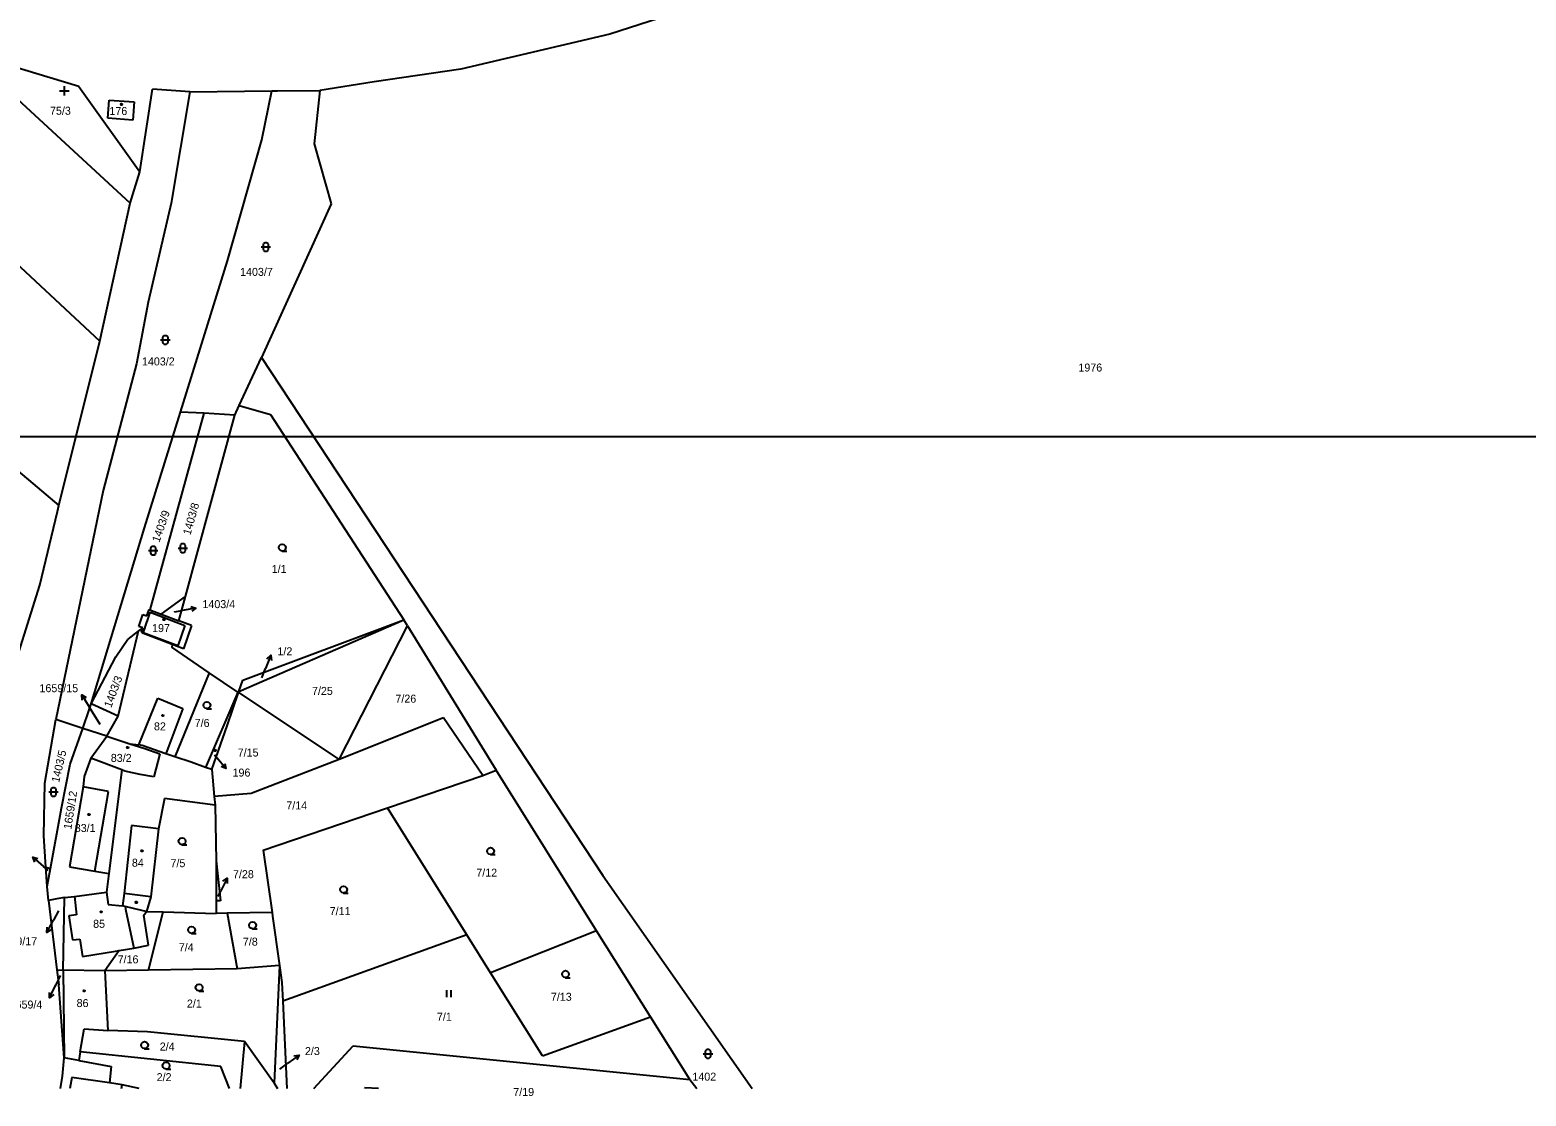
# Model space of a CAD drawing. Extents: x -801853 to -800578, y -1017479 to -1016338.
# Drawn here: x -801488.1 to -801170.2, y -1017479.3 to -1017252.6 of the extents above; entities that cross this region are included whole.
import ezdxf

# ---------------------------------------------------------------- set-up
doc = ezdxf.new("R2010")
doc.units = 0
for name, color, linetype in [('Default', 7, 'Continuous'), ('KN_HRANICE', 7, 'Continuous'), ('KN_KULTURY', 7, 'Continuous'), ('KN_PARCELY', 7, 'Continuous'), ('KN_SLUCKY', 7, 'Continuous'), ('LEGENDA', 7, 'Continuous')]:
    doc.layers.add(name, color=color, linetype=linetype)

# ---------------------------------------------------------------- blocks, each defined once
blk = doc.blocks.new('304')
at = {"layer": 'Default'}
blk.add_lwpolyline([(0, 0), (-0.38, 0.1), (-0.65, 0.37), (-0.75, 0.74), (-0.65, 1.11), (-0.38, 1.38), (-0.01, 1.48), (0.36, 1.38), (0.63, 1.11), (0.73, 0.73), (0.63, 0.35), (0.36, 0.08), (-0.02, -0.02), (0.98, -0.02)], dxfattribs=at)
blk = doc.blocks.new('306')
at = {"layer": 'Default'}
for p, q in [((-0.5, 1.5), (-0.5, 0)), ((0.5, 0), (0.5, 1.5))]:
    blk.add_line(p, q, dxfattribs=at)
blk = doc.blocks.new('315')
at = {"layer": 'Default'}
for p, q in [((-1, 1), (1, 1)), ((0, 0), (0, 2))]:
    blk.add_line(p, q, dxfattribs=at)
blk = doc.blocks.new('316')
at = {"layer": 'Default'}
for points in [[(-1, 1), (0.27, 1), (1, 1)], [(-0.5, 1.5), (-0.4, 1.79), (-0.15, 1.97), (0.16, 1.97), (0.41, 1.79), (0.51, 1.5), (0.51, 0.5), (0.41, 0.21), (0.16, 0.03), (-0.15, 0.03), (-0.4, 0.21), (-0.5, 0.5), (-0.5, 1.5)]]:
    blk.add_lwpolyline(points, dxfattribs=at)
blk = doc.blocks.new('NAHRADNI_SYMBOL')
at = {"layer": 'Default'}
blk.add_lwpolyline([(0.09, 0.15), (0.18, 0), (0.09, -0.15), (-0.09, -0.15), (-0.18, 0), (-0.09, 0.15), (0.09, 0.15)], dxfattribs=at)
blk = doc.blocks.new('10292')
at = {"layer": 'Default'}
blk.add_line((0, 3), (0, 0), dxfattribs=at)
blk.add_lwpolyline([(-0.5, 2), (0, 3), (0.5, 2)], dxfattribs=at)
blk = doc.blocks.new('402')
at = {"layer": 'Default'}
blk.add_lwpolyline([(0.09, 0.15), (0.18, 0), (0.09, -0.15), (-0.09, -0.15), (-0.18, 0), (-0.09, 0.15), (0.09, 0.15)], dxfattribs=at)

msp = doc.modelspace()

# ---------------------------------------------------------------- linework, layer by layer
at = {"layer": 'KN_HRANICE'}
for p, q in [((-801619.51, -1017238.39), (-801481.95, -1017353.71)), ((-801318.92, -1017238.69), (-801364.93, -1017253.53)), ((-801364.93, -1017253.53), (-801396.54, -1017260.97)), ((-801477.73, -1017264.63), (-801501.56, -1017257.45)), ((-801466.82, -1017289.45), (-801501.56, -1017257.45)), ((-801396.54, -1017260.97), (-801415.01, -1017263.64)), ((-801477.73, -1017264.63), (-801464.79, -1017282.78)), ((-801464.79, -1017282.78), (-801462.07, -1017265.26)), ((-801454.13, -1017265.82), (-801462.07, -1017265.26)), ((-801415.01, -1017263.64), (-801426.49, -1017265.49)), ((-801471.6, -1017271.43), (-801471.3, -1017267.55)), ((-801471.3, -1017267.55), (-801466, -1017267.95)), ((-801466, -1017267.95), (-801466.29, -1017271.83)), ((-801454.13, -1017265.82), (-801458.15, -1017289.48)), ((-801454.13, -1017265.82), (-801436.73, -1017265.61)), ((-801438.87, -1017276.02), (-801436.73, -1017265.61)), ((-801436.73, -1017265.61), (-801435.52, -1017265.6)), ((-801435.52, -1017265.6), (-801426.49, -1017265.49)), ((-801426.49, -1017265.49), (-801427.72, -1017276.85)), ((-801466.29, -1017271.83), (-801471.6, -1017271.43)), ((-801473.28, -1017318.78), (-801518.94, -1017276.33)), ((-801446.14, -1017301.75), (-801438.87, -1017276.02)), ((-801427.72, -1017276.85), (-801424.14, -1017289.58)), ((-801466.82, -1017289.45), (-801464.79, -1017282.78)), ((-801473.28, -1017318.78), (-801466.82, -1017289.45)), ((-801458.15, -1017289.48), (-801462.97, -1017310.53)), ((-801424.14, -1017289.58), (-801438.92, -1017322.27)), ((-801456.12, -1017333.87), (-801446.14, -1017301.75)), ((-801462.97, -1017310.53), (-801465.45, -1017323.65)), ((-801481.95, -1017353.71), (-801473.28, -1017318.78)), ((-801443.65, -1017332.48), (-801438.92, -1017322.27)), ((-801438.92, -1017322.27), (-801366.39, -1017432.38)), ((-801465.45, -1017323.65), (-801472.56, -1017350.57)), ((-801463.78, -1017358.51), (-801456.12, -1017333.87)), ((-801451.19, -1017334.14), (-801462.64, -1017375.93)), ((-801451.19, -1017334.14), (-801456.12, -1017333.87)), ((-801455.08, -1017373.05), (-801444.59, -1017334.5)), ((-801444.59, -1017334.5), (-801451.19, -1017334.14)), ((-801444.59, -1017334.5), (-801443.65, -1017332.48)), ((-801443.65, -1017332.48), (-801437.03, -1017334.42)), ((-801437.03, -1017334.42), (-801408.69, -1017378.05)), ((-801472.56, -1017350.57), (-801482.61, -1017399.26)), ((-801482.28, -1017355.03), (-801481.95, -1017353.71)), ((-801486.04, -1017370.69), (-801482.28, -1017355.03)), ((-801475.12, -1017395.87), (-801463.78, -1017358.51)), ((-801493.03, -1017393.07), (-801486.04, -1017370.69)), ((-801460.21, -1017376.86), (-801455.08, -1017373.05)), ((-801456.5, -1017378.26), (-801455.08, -1017373.05)), ((-801463.26, -1017377.18), (-801462.81, -1017375.87)), ((-801462.81, -1017375.87), (-801462.64, -1017375.93)), ((-801462.64, -1017375.93), (-801460.21, -1017376.86)), ((-801464.14, -1017379.72), (-801465.04, -1017380.4)), ((-801464.99, -1017379.43), (-801464.11, -1017376.89)), ((-801464.14, -1017379.72), (-801464.99, -1017379.43)), ((-801464.45, -1017380.63), (-801464.14, -1017379.72)), ((-801464.11, -1017376.89), (-801463.26, -1017377.18)), ((-801460.21, -1017376.86), (-801456.5, -1017378.26)), ((-801453.76, -1017379.27), (-801456.5, -1017378.26)), ((-801453.76, -1017379.27), (-801455.47, -1017384.17)), ((-801443.73, -1017393.29), (-801408.69, -1017378.05)), ((-801442.91, -1017390.9), (-801408.69, -1017378.05)), ((-801422.42, -1017407.74), (-801407.88, -1017379.29)), ((-801407.88, -1017379.29), (-801408.69, -1017378.05)), ((-801407.88, -1017379.29), (-801389.06, -1017410.03)), ((-801469.88, -1017385.9), (-801467.33, -1017382.12)), ((-801469.37, -1017398.55), (-801465.04, -1017380.4)), ((-801465.04, -1017380.4), (-801467.33, -1017382.12)), ((-801464.01, -1017380.93), (-801464.45, -1017380.63)), ((-801457.88, -1017383.3), (-801464.01, -1017380.93)), ((-801475.12, -1017395.87), (-801469.88, -1017385.9)), ((-801457.88, -1017383.3), (-801458, -1017383.82)), ((-801450.03, -1017389.33), (-801458, -1017383.82)), ((-801455.47, -1017384.17), (-801457.88, -1017383.3)), ((-801450.03, -1017389.33), (-801457.32, -1017407.16)), ((-801443.97, -1017393.39), (-801450.03, -1017389.33)), ((-801443.73, -1017393.29), (-801442.91, -1017390.9)), ((-801443.97, -1017393.39), (-801450.79, -1017409.43)), ((-801446.23, -1017400.56), (-801443.8, -1017393.5)), ((-801443.97, -1017393.39), (-801443.73, -1017393.29)), ((-801443.8, -1017393.5), (-801443.73, -1017393.29)), ((-801443.8, -1017393.5), (-801422.42, -1017407.74)), ((-801476.91, -1017401.11), (-801475.51, -1017397.16)), ((-801475.51, -1017397.16), (-801475.12, -1017395.87)), ((-801469.37, -1017398.55), (-801475.12, -1017395.87)), ((-801471.82, -1017402.77), (-801469.37, -1017398.55)), ((-801400.24, -1017398.84), (-801422.42, -1017407.74)), ((-801391.91, -1017411.13), (-801400.24, -1017398.84)), ((-801484.97, -1017412.74), (-801482.61, -1017399.26)), ((-801476.91, -1017401.11), (-801482.61, -1017399.26)), ((-801479.6, -1017408.7), (-801476.91, -1017401.11)), ((-801471.82, -1017402.77), (-801476.91, -1017401.11)), ((-801449.49, -1017409.89), (-801446.23, -1017400.56)), ((-801475.18, -1017407.42), (-801471.82, -1017402.77)), ((-801471.82, -1017402.77), (-801466.9, -1017404.38)), ((-801466.9, -1017404.38), (-801463.71, -1017405.36)), ((-801466.9, -1017404.38), (-801464.99, -1017404.58)), ((-801464.3, -1017404.78), (-801464.99, -1017404.58)), ((-801459.24, -1017406.5), (-801464.3, -1017404.78)), ((-801475.18, -1017407.42), (-801476.57, -1017411.34)), ((-801468.57, -1017409.95), (-801475.18, -1017407.42)), ((-801463.71, -1017405.36), (-801460.5, -1017406.5)), ((-801460.5, -1017406.5), (-801461.81, -1017411.42)), ((-801457.32, -1017407.16), (-801459.24, -1017406.5)), ((-801453.89, -1017408.33), (-801457.32, -1017407.16)), ((-801450.79, -1017409.43), (-801453.89, -1017408.33)), ((-801422.42, -1017407.74), (-801441.13, -1017414.93)), ((-801481.43, -1017418.11), (-801479.6, -1017408.7)), ((-801476.57, -1017411.34), (-801476.78, -1017413.57)), ((-801468.57, -1017409.95), (-801471.37, -1017431.95)), ((-801467.94, -1017410.19), (-801468.57, -1017409.95)), ((-801464.69, -1017410.9), (-801467.94, -1017410.19)), ((-801461.81, -1017411.42), (-801464.69, -1017410.9)), ((-801449.49, -1017409.89), (-801450.79, -1017409.43)), ((-801449.49, -1017409.89), (-801448.95, -1017415.59)), ((-801412.18, -1017418.02), (-801391.91, -1017411.13)), ((-801391.91, -1017411.13), (-801389.06, -1017410.03)), ((-801367.72, -1017444.15), (-801389.06, -1017410.03)), ((-801485.18, -1017423.98), (-801484.97, -1017412.74)), ((-801476.78, -1017413.57), (-801479.73, -1017430.52)), ((-801459.51, -1017416.03), (-801460.82, -1017422.5)), ((-801448.78, -1017417.45), (-801459.51, -1017416.03)), ((-801441.13, -1017414.93), (-801448.95, -1017415.59)), ((-801448.95, -1017415.59), (-801448.78, -1017417.45)), ((-801448.78, -1017417.45), (-801448.56, -1017429.24)), ((-801483.75, -1017430.88), (-801481.43, -1017418.11)), ((-801438.55, -1017426.97), (-801412.18, -1017418.02)), ((-801395.3, -1017445.02), (-801412.18, -1017418.02)), ((-801484.77, -1017430.63), (-801485.18, -1017423.98)), ((-801460.82, -1017422.5), (-801462.42, -1017436.96)), ((-801438.55, -1017426.97), (-801436.67, -1017440.26)), ((-801484.44, -1017434.71), (-801484.77, -1017430.63)), ((-801484.77, -1017430.63), (-801483.75, -1017430.88)), ((-801479.73, -1017430.52), (-801474.31, -1017431.46)), ((-801448.56, -1017429.24), (-801447.64, -1017437.77)), ((-801448.56, -1017429.24), (-801448.55, -1017437.77)), ((-801484.44, -1017434.71), (-801483.75, -1017430.88)), ((-801474.31, -1017431.46), (-801471.37, -1017431.95)), ((-801471.37, -1017431.95), (-801471.88, -1017435.96)), ((-801366.39, -1017432.38), (-801334.68, -1017477.65)), ((-801484.2, -1017437.73), (-801484.44, -1017434.71)), ((-801480.79, -1017437.04), (-801482.44, -1017437.37)), ((-801481.05, -1017452.5), (-801480.79, -1017437.04)), ((-801480.79, -1017437.04), (-801478.66, -1017436.87)), ((-801478.66, -1017436.87), (-801471.88, -1017435.96)), ((-801471.88, -1017435.96), (-801471.48, -1017438.57)), ((-801462.42, -1017436.96), (-801463.38, -1017440.03)), ((-801482.44, -1017437.37), (-801484.2, -1017437.73)), ((-801484.2, -1017437.73), (-801482.44, -1017452.42)), ((-801471.48, -1017438.57), (-801468.43, -1017438.86)), ((-801467.91, -1017438.98), (-801468.43, -1017438.86)), ((-801464.08, -1017439.87), (-801467.91, -1017438.98)), ((-801463.38, -1017440.03), (-801464.08, -1017439.87)), ((-801463.93, -1017440.81), (-801463.38, -1017440.03)), ((-801463.38, -1017440.03), (-801459.78, -1017440.14)), ((-801462.91, -1017452.5), (-801459.78, -1017440.14)), ((-801459.78, -1017440.14), (-801448.54, -1017440.47)), ((-801447.64, -1017437.77), (-801448.55, -1017437.77)), ((-801448.55, -1017437.77), (-801448.54, -1017440.47)), ((-801436.67, -1017440.26), (-801446.24, -1017440.43)), ((-801436.67, -1017440.26), (-801436.56, -1017441.04)), ((-801462.92, -1017447.17), (-801463.93, -1017440.81)), ((-801446.24, -1017440.43), (-801448.54, -1017440.47)), ((-801446.24, -1017440.43), (-801444.06, -1017452.22)), ((-801436.56, -1017441.04), (-801435.08, -1017451.54)), ((-801395.3, -1017445.02), (-801434.42, -1017459.09)), ((-801390.25, -1017453.11), (-801395.3, -1017445.02)), ((-801367.72, -1017444.15), (-801390.25, -1017453.11)), ((-801356.25, -1017462.47), (-801367.72, -1017444.15)), ((-801469.2, -1017448.34), (-801472.2, -1017452.64)), ((-801469.2, -1017448.34), (-801466.08, -1017447.84)), ((-801466.08, -1017447.84), (-801462.92, -1017447.17)), ((-801482.44, -1017452.42), (-801481.05, -1017452.5)), ((-801482.44, -1017452.42), (-801481.99, -1017455.66)), ((-801472.2, -1017452.64), (-801481.05, -1017452.5)), ((-801481.05, -1017452.5), (-801480.85, -1017471.15)), ((-801462.91, -1017452.5), (-801472.2, -1017452.64)), ((-801472.2, -1017452.64), (-801471.55, -1017465.31)), ((-801444.06, -1017452.22), (-801462.91, -1017452.5)), ((-801435.08, -1017451.54), (-801444.06, -1017452.22)), ((-801435.08, -1017451.54), (-801436.26, -1017476.56)), ((-801435.08, -1017451.54), (-801434.61, -1017455.17)), ((-801480.85, -1017471.15), (-801481.99, -1017455.66)), ((-801434.61, -1017455.17), (-801434.42, -1017459.09)), ((-801379.24, -1017470.71), (-801390.25, -1017453.11)), ((-801434.42, -1017459.09), (-801433.51, -1017477.65)), ((-801379.24, -1017470.71), (-801356.25, -1017462.47)), ((-801347.93, -1017475.78), (-801356.25, -1017462.47)), ((-801477.42, -1017469.86), (-801476.6, -1017465.01)), ((-801476.6, -1017465.01), (-801471.55, -1017465.31)), ((-801463.11, -1017465.64), (-801471.55, -1017465.31)), ((-801442.53, -1017467.71), (-801463.11, -1017465.64)), ((-801442.53, -1017467.71), (-801443.44, -1017477.65)), ((-801436.26, -1017476.56), (-801442.53, -1017467.71)), ((-801427.81, -1017477.65), (-801419.41, -1017468.61)), ((-801419.41, -1017468.61), (-801347.93, -1017475.78)), ((-801481.2, -1017475.07), (-801480.85, -1017471.15)), ((-801477.74, -1017471.72), (-801480.85, -1017471.15)), ((-801477.42, -1017469.86), (-801477.74, -1017471.72)), ((-801477.74, -1017471.72), (-801470.85, -1017473.01)), ((-801447.58, -1017472.97), (-801477.42, -1017469.86)), ((-801481.66, -1017477.65), (-801481.2, -1017475.07)), ((-801470.85, -1017473.01), (-801471.25, -1017476.47)), ((-801445.72, -1017477.65), (-801447.58, -1017472.97)), ((-801468.51, -1017476.86), (-801471.25, -1017476.47)), ((-801464.93, -1017477.65), (-801468.51, -1017476.86)), ((-801436.26, -1017476.56), (-801435.53, -1017477.65)), ((-801416.99, -1017477.52), (-801417, -1017477.65)), ((-801414.05, -1017477.65), (-801416.99, -1017477.52)), ((-801347.93, -1017475.78), (-801346.4, -1017477.65))]:
    msp.add_line(p, q, dxfattribs=at)
at = {"layer": 'KN_PARCELY'}
for p, q in [((-801457.41, -1017376.35), (-801455.81, -1017376.07)), ((-801438.84, -1017390.35), (-801438.04, -1017388.36)), ((-801473.22, -1017400.28), (-801475.54, -1017396.53)), ((-801448.9, -1017406.77), (-801448.4, -1017407.37)), ((-801484.27, -1017431.32), (-801485.23, -1017430.49)), ((-801448.16, -1017436.83), (-801447.56, -1017435.64)), ((-801482.04, -1017439.87), (-801483.1, -1017441.87)), ((-801481.69, -1017453.66), (-801482.65, -1017455.66)), ((-801435.04, -1017473.53), (-801433.36, -1017472.32))]:
    msp.add_line(p, q, dxfattribs=at)
at = {"layer": 'KN_SLUCKY'}
for p, q in [((-801462.86, -1017377.32), (-801462.55, -1017376.41)), ((-801462.55, -1017376.41), (-801455.19, -1017379.23)), ((-801464.05, -1017380.77), (-801463.74, -1017379.86)), ((-801463.74, -1017379.86), (-801463.58, -1017379.36)), ((-801463.58, -1017379.36), (-801462.86, -1017377.32)), ((-801455.19, -1017379.23), (-801456.68, -1017383.56)), ((-801456.68, -1017383.56), (-801464.05, -1017380.77)), ((-801464.99, -1017404.58), (-801460.92, -1017394.66)), ((-801460.92, -1017394.66), (-801455.63, -1017396.89)), ((-801455.63, -1017396.89), (-801459.24, -1017406.5)), ((-801471.46, -1017414.5), (-801476.78, -1017413.57)), ((-801474.31, -1017431.46), (-801471.46, -1017414.5)), ((-801466.53, -1017421.73), (-801468.13, -1017436.19)), ((-801460.82, -1017422.5), (-801466.53, -1017421.73)), ((-801478.66, -1017436.87), (-801478.26, -1017440.73)), ((-801468.13, -1017436.19), (-801468.43, -1017438.86)), ((-801462.42, -1017436.96), (-801468.13, -1017436.19)), ((-801467.91, -1017438.98), (-801467.8, -1017439.52)), ((-801467.8, -1017439.52), (-801466.08, -1017447.84)), ((-801478.26, -1017440.73), (-801479.84, -1017440.98)), ((-801479.84, -1017440.98), (-801479.1, -1017446.07)), ((-801479.1, -1017446.07), (-801477.5, -1017445.91)), ((-801477.5, -1017445.91), (-801476.98, -1017449.6)), ((-801476.98, -1017449.6), (-801469.95, -1017448.47)), ((-801469.95, -1017448.47), (-801469.2, -1017448.34)), ((-801479.23, -1017475.34), (-801479.64, -1017477.65)), ((-801471.25, -1017476.47), (-801479.23, -1017475.34)), ((-801468.7, -1017477.65), (-801468.51, -1017476.86))]:
    msp.add_line(p, q, dxfattribs=at)
at = {"layer": 'LEGENDA'}
msp.add_lwpolyline([(-801559.16, -1017339.08), (-800718.16, -1017339.08), (-800718.16, -1016745.08), (-801559.16, -1016745.08)], close=True, dxfattribs=at)

# ---------------------------------------------------------------- block references
at = {"layer": 'KN_KULTURY'}
for name, p in [('315', (-801480.81, -1017266.56)), ('402', (-801468.66, -1017268.45)), ('316', (-801438.02, -1017299.77)), ('316', (-801459.36, -1017319.54)), ('316', (-801461.92, -1017364.33)), ('316', (-801455.63, -1017363.81)), ('304', (-801434.51, -1017363.42)), ('402', (-801459.63, -1017377.97)), ('304', (-801450.51, -1017396.92)), ('402', (-801459.9, -1017398.39)), ('402', (-801467.35, -1017405.18)), ('NAHRADNI_SYMBOL', (-801448.77, -1017405.79)), ('316', (-801483.13, -1017415.62)), ('402', (-801475.59, -1017419.42)), ('304', (-801455.8, -1017425.84)), ('402', (-801464.3, -1017427.17)), ('304', (-801390.23, -1017427.94)), ('304', (-801421.48, -1017436.11)), ('402', (-801472.99, -1017440.12)), ('402', (-801465.5, -1017438.1)), ('304', (-801453.78, -1017444.69)), ('304', (-801440.79, -1017443.71)), ('304', (-801374.31, -1017454.09)), ('304', (-801452.18, -1017456.94)), ('NAHRADNI_SYMBOL', (-801476.59, -1017456.92)), ('306', (-801399.14, -1017458.26)), ('304', (-801463.74, -1017469.19)), ('316', (-801344.05, -1017471.3)), ('304', (-801459.19, -1017473.55))]:
    msp.add_blockref(name, p, dxfattribs=at)
at = {"layer": 'KN_PARCELY'}
for p, rotation in [((-801455.81, -1017376.07), -80.05282100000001), ((-801438.04, -1017388.36), -21.897605), ((-801475.54, -1017396.53), 31.741862), ((-801448.4, -1017407.37), -139.81231900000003), ((-801485.23, -1017430.49), 49.15977900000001), ((-801447.56, -1017435.64), -26.595858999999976), ((-801483.1, -1017441.87), 152.005703), ((-801482.65, -1017455.66), 154.469422), ((-801433.36, -1017472.32), -54.155129)]:
    msp.add_blockref('10292', p, dxfattribs=dict(at, rotation=rotation))

# ---------------------------------------------------------------- texts
for s, height, p in [('75/3', 1.7, (-801483.86, -1017270.67)), ('176', 1.7, (-801471.24, -1017270.72)), ('1403/7', 1.7, (-801443.47, -1017304.92)), ('1403/2', 1.7, (-801464.32, -1017323.96)), ('1976', 1.7, (-801265.34, -1017325.26)), ('1/1', 1.7, (-801436.75, -1017368.08)), ('1403/4', 0.1, (-801457.71, -1017376.35)), ('1403/4', 1.7, (-801451.47, -1017375.55)), ('197', 1.7, (-801462.17, -1017380.64)), ('1/2', 1.7, (-801435.53, -1017385.58)), ('1659/15', 1.7, (-801486.1, -1017393.42)), ('1/2', 0.1, (-801438.99, -1017390.35)), ('7/25', 1.7, (-801428.19, -1017394)), ('7/26', 1.7, (-801410.47, -1017395.65)), ('1659/15', 0.1, (-801473.57, -1017400.28)), ('82', 1.7, (-801461.77, -1017401.54)), ('7/6', 1.7, (-801453.12, -1017400.81)), ('83/2', 1.7, (-801470.94, -1017408.24)), ('196', 0.1, (-801449.05, -1017406.77)), ('7/15', 1.7, (-801443.97, -1017407.1)), ('196', 1.7, (-801445.07, -1017411.36)), ('7/14', 1.7, (-801433.65, -1017418.35)), ('83/1', 1.7, (-801478.6, -1017423.14)), ('84', 1.7, (-801466.46, -1017430.53)), ('7/5', 1.7, (-801458.26, -1017430.62)), ('1403/6', 0.1, (-801484.57, -1017431.32)), ('7/28', 1.7, (-801444.98, -1017432.96)), ('7/12', 1.7, (-801393.28, -1017432.64)), ('7/28', 0.1, (-801448.36, -1017436.83)), ('1659/17', 0.1, (-801482.39, -1017439.87)), ('7/11', 1.7, (-801424.43, -1017440.81)), ('85', 1.7, (-801474.7, -1017443.51)), ('1659/17', 1.7, (-801494.8, -1017447.21)), ('7/8', 1.7, (-801442.88, -1017447.3)), ('7/16', 1.7, (-801469.49, -1017451.06)), ('7/4', 1.7, (-801456.5, -1017448.5)), ('1659/4', 0.1, (-801481.99, -1017453.66)), ('1659/4', 1.7, (-801492.44, -1017460.67)), ('86', 1.7, (-801478.21, -1017460.36)), ('2/1', 1.7, (-801454.77, -1017460.46)), ('7/13', 1.7, (-801377.43, -1017459.02)), ('7/1', 1.7, (-801401.65, -1017463.26)), ('2/4', 1.7, (-801460.54, -1017469.6)), ('2/3', 1.7, (-801429.69, -1017470.56)), ('2/2', 1.7, (-801461.2, -1017476.11)), ('2/3', 0.1, (-801435.19, -1017473.53)), ('1402', 1.7, (-801347.36, -1017476)), ('7/19', 1.7, (-801385.42, -1017479.26))]:
    msp.add_text(s, height=height, dxfattribs=at).set_placement(p)
for s, rotation, p in [('1403/8', 74.141, (-801454.03, -1017360.14)), ('1403/9', 70.703, (-801460.64, -1017361.7)), ('1403/3', 69.614, (-801470.86, -1017396.86)), ('1403/5', 76.834, (-801481.93, -1017412.74)), ('1659/12', 81.245, (-801479.33, -1017422.67))]:
    msp.add_text(s, height=1.7, rotation=rotation, dxfattribs=at).set_placement(p)

doc.saveas('drawing.dxf')
